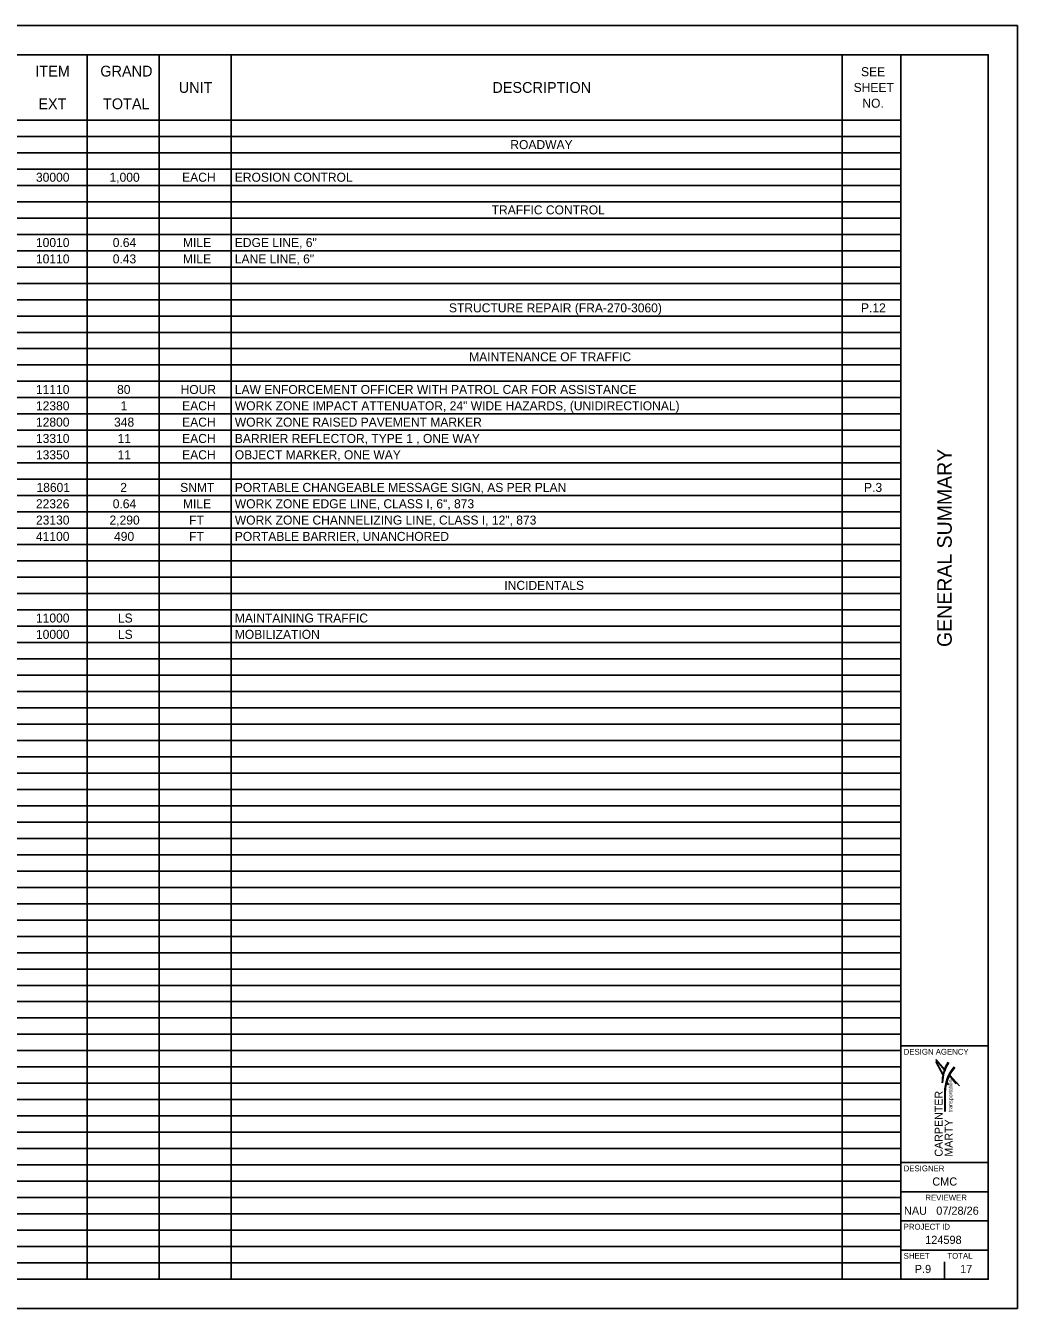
# Model space of a CAD drawing. Extents: x 0 to 34, y 0 to 22.
# Drawn here: x 16.99 to 34, y 0 to 22 of the extents above; entities that cross this region are included whole.
import ezdxf

# ---------------------------------------------------------------- set-up
doc = ezdxf.new("R2010")
doc.units = 0
for name, color, linetype in [('Default', 7, 'Continuous'), ('SH_Border', 7, 'Continuous'), ('SH_Cut_Line', 7, 'Continuous'), ('SH_Data', 7, 'Continuous'), ('SH_Text', 7, 'Continuous')]:
    doc.layers.add(name, color=color, linetype=linetype)

msp = doc.modelspace()

# ---------------------------------------------------------------- linework, layer by layer
at = {"layer": 'Default'}
for p, q in [((1.5, 21.5), (32, 21.5)), ((18.04308, 21.5), (18.04308, 0.5)), ((19.27858, 21.5), (19.27858, 0.5)), ((20.51407, 21.5), (20.51407, 0.5)), ((30.99485, 21.5), (30.99485, 0.5)), ((32, 21.5), (32, 0.5)), ((1.5, 20.38), (32, 20.38)), ((1.5, 20.1), (32, 20.1)), ((1.5, 19.82), (32, 19.82)), ((1.5, 19.54), (32, 19.54)), ((1.5, 19.26), (32, 19.26)), ((1.5, 18.98), (32, 18.98)), ((1.5, 18.7), (32, 18.7)), ((1.5, 18.42), (32, 18.42)), ((1.5, 18.14), (32, 18.14)), ((1.5, 17.86), (32, 17.86)), ((1.5, 17.58), (32, 17.58)), ((1.5, 17.3), (32, 17.3)), ((1.5, 17.02), (32, 17.02)), ((1.5, 16.74), (32, 16.74)), ((1.5, 16.46), (32, 16.46)), ((1.5, 16.18), (32, 16.18)), ((1.5, 15.9), (32, 15.9)), ((1.5, 15.62), (32, 15.62)), ((1.5, 15.34), (32, 15.34)), ((1.5, 15.06), (32, 15.06)), ((1.5, 14.78), (32, 14.78)), ((1.5, 14.5), (32, 14.5)), ((1.5, 14.22), (32, 14.22)), ((1.5, 13.94), (32, 13.94)), ((1.5, 13.66), (32, 13.66)), ((1.5, 13.38), (32, 13.38)), ((1.5, 13.1), (32, 13.1)), ((1.5, 12.82), (32, 12.82)), ((1.5, 12.54), (32, 12.54)), ((1.5, 12.26), (32, 12.26)), ((1.5, 11.98), (32, 11.98)), ((1.5, 11.7), (32, 11.7)), ((1.5, 11.42), (32, 11.42)), ((1.5, 11.14), (32, 11.14)), ((1.5, 10.86), (32, 10.86)), ((1.5, 10.58), (32, 10.58)), ((1.5, 10.3), (32, 10.3)), ((1.5, 10.02), (32, 10.02)), ((1.5, 9.74), (32, 9.74)), ((1.5, 9.46), (32, 9.46)), ((1.5, 9.18), (32, 9.18)), ((1.5, 8.9), (32, 8.9)), ((1.5, 8.62), (32, 8.62)), ((1.5, 8.34), (32, 8.34)), ((1.5, 8.06), (32, 8.06)), ((1.5, 7.78), (32, 7.78)), ((1.5, 7.5), (32, 7.5)), ((1.5, 7.22), (32, 7.22)), ((1.5, 6.94), (32, 6.94)), ((1.5, 6.66), (32, 6.66)), ((1.5, 6.38), (32, 6.38)), ((1.5, 6.1), (32, 6.1)), ((1.5, 5.82), (32, 5.82)), ((1.5, 5.54), (32, 5.54)), ((1.5, 5.26), (32, 5.26)), ((1.5, 4.98), (32, 4.98)), ((1.5, 4.7), (32, 4.7)), ((1.5, 4.42), (32, 4.42)), ((1.5, 4.14), (32, 4.14)), ((1.5, 3.86), (32, 3.86)), ((1.5, 3.58), (32, 3.58)), ((1.5, 3.3), (32, 3.3)), ((1.5, 3.02), (32, 3.02)), ((1.5, 2.74), (32, 2.74)), ((1.5, 2.46), (32, 2.46)), ((1.5, 2.18), (32, 2.18)), ((1.5, 1.9), (32, 1.9)), ((1.5, 1.62), (32, 1.62)), ((1.5, 1.34), (32, 1.34)), ((1.5, 1.06), (32, 1.06)), ((1.5, 0.78), (32, 0.78)), ((1.5, 0.5), (32, 0.5))]:
    msp.add_line(p, q, dxfattribs=at)
at = {"layer": 'SH_Border'}
for p, q in [((32, 0.5), (32, 21.5)), ((32, 4.5), (33.5, 4.5)), ((32, 2.5), (33.5, 2.5)), ((32, 2), (33.5, 2)), ((32, 1.5), (33.5, 1.5)), ((32, 1), (33.5, 1))]:
    msp.add_line(p, q, dxfattribs=at)
msp.add_lwpolyline([(1.5, 21.5), (33.5, 21.5), (33.5, 0.5), (1.5, 0.5)], close=True, dxfattribs=at)
at = {"layer": 'SH_Cut_Line'}
msp.add_lwpolyline([(0, 0), (34, 0), (34, 22), (0, 22)], close=True, dxfattribs=at)
at = {"layer": 'SH_Data'}
for p, q in [((32.75, 3.5), (32.75, 3.5)), ((32.375, 0.675), (32.375, 0.675)), ((32.75, 0.5), (32.75, 0.8))]:
    msp.add_line(p, q, dxfattribs=at)
at = {"layer": 'SH_Text'}
for p, q in [((32.72069, 4.01649), (32.60162, 4.23177)), ((32.95166, 3.8527), (32.83407, 3.99137)), ((32.83913, 4.00169), (33.00597, 3.81618)), ((32.8109, 3.84047), (32.78964, 3.88)), ((32.82016, 3.83352), (32.79149, 3.88608)), ((32.755, 3.3776), (32.755, 3.70391)), ((32.76174, 3.3776), (32.76174, 3.70408))]:
    msp.add_line(p, q, dxfattribs=at)
for points in [[(32.74615, 4.10431), (32.60113, 4.26615)], [(32.60113, 4.26605), (32.74381, 4.0978)], [(32.72069, 4.01649), (32.60162, 4.23177)], [(32.60162, 4.23173), (32.71946, 4.01079)]]:
    msp.add_lwpolyline(points, dxfattribs=at)
for centre, radius, start, end in [((33.4324, 3.85993), 0.72071, 149.570417, 179.552883), ((33.37304, 3.86159), 0.65428, 147.142265, 179.652527), ((33.42552, 3.70404), 0.67052, 139.289845, 180.01062), ((33.43327, 3.68775), 0.67173, 138.512563, 178.6075)]:
    msp.add_arc(centre, radius, start, end, dxfattribs=at)

# ---------------------------------------------------------------- texts
at = {"layer": 'Default'}
for s, height, p in [('ITEM', 0.185472, (17.15496, 21.12726)), ('GRAND', 0.185472, (18.26982, 21.12726)), ('SEE ', 0.15456, (31.31887, 21.1332)), ('UNIT', 0.185472, (19.61506, 20.84726)), ('DESCRIPTION', 0.185472, (24.9946, 20.84726)), ('SHEET ', 0.15456, (31.19159, 20.86272)), ('EXT', 0.185472, (17.20667, 20.56726)), ('TOTAL', 0.185472, (18.31574, 20.56726)), ('NO.', 0.15456, (31.34138, 20.59224)), ('ROADWAY', 0.15456, (25.30316, 19.88272)), ('30000', 0.15456, (17.16611, 19.32272)), ('1,000', 0.15456, (18.42792, 19.32272)), ('EACH', 0.15456, (19.67367, 19.32272)), ('EROSION CONTROL', 0.15456, (20.5769, 19.32272)), ('TRAFFIC CONTROL', 0.15456, (24.98295, 18.76272)), ('10010', 0.15456, (17.16611, 18.20272)), ('0.64', 0.15456, (18.48299, 18.20272)), ('MILE', 0.15456, (19.68796, 18.20272)), ('EDGE LINE, 6"', 0.15456, (20.5769, 18.20272)), ('10110', 0.15456, (17.16611, 17.92272)), ('0.43', 0.15456, (18.48299, 17.92272)), ('MILE', 0.15456, (19.68796, 17.92272)), ('LANE LINE, 6"', 0.15456, (20.5769, 17.92272)), ('STRUCTURE REPAIR (FRA-270-3060)', 0.15456, (24.25026, 17.08272)), ('P.12', 0.15456, (31.31818, 17.08272)), ('MAINTENANCE OF TRAFFIC', 0.15456, (24.59704, 16.24272)), ('11110', 0.15456, (17.16611, 15.68272)), ('80', 0.15456, (18.55729, 15.68272)), ('HOUR', 0.15456, (19.64662, 15.68272)), ('LAW ENFORCEMENT OFFICER WITH PATROL CAR FOR ASSISTANCE', 0.15456, (20.5769, 15.68272)), ('12380', 0.15456, (17.16611, 15.40272)), ('1', 0.15456, (18.61828, 15.40272)), ('EACH', 0.15456, (19.67367, 15.40272)), ('WORK ZONE IMPACT ATTENUATOR, 24" WIDE HAZARDS, (UNIDIRECTIONAL)', 0.15456, (20.5769, 15.40272)), ('12800', 0.15456, (17.16611, 15.12272)), ('348', 0.15456, (18.50594, 15.12272)), ('EACH', 0.15456, (19.67367, 15.12272)), ('WORK ZONE RAISED PAVEMENT MARKER', 0.15456, (20.5769, 15.12272)), ('13310', 0.15456, (17.16611, 14.84272)), ('11', 0.15456, (18.56638, 14.84272)), ('EACH', 0.15456, (19.67367, 14.84272)), ('BARRIER REFLECTOR, TYPE 1 , ONE WAY', 0.15456, (20.5769, 14.84272)), ('13350', 0.15456, (17.16611, 14.56272)), ('11', 0.15456, (18.56638, 14.56272)), ('EACH', 0.15456, (19.67367, 14.56272)), ('OBJECT MARKER, ONE WAY', 0.15456, (20.5769, 14.56272)), ('18601', 0.15456, (17.1752, 14.00272)), ('2', 0.15456, (18.61229, 14.00272)), ('SNMT', 0.15456, (19.6393, 14.00272)), ('PORTABLE CHANGEABLE MESSAGE SIGN, AS PER PLAN', 0.15456, (20.5769, 14.00272)), ('P.3', 0.15456, (31.37044, 14.00272)), ('22326', 0.15456, (17.16556, 13.72272)), ('0.64', 0.15456, (18.48299, 13.72272)), ('MILE', 0.15456, (19.68796, 13.72272)), ('WORK ZONE EDGE LINE, CLASS I, 6", 873', 0.15456, (20.5769, 13.72272)), ('23130', 0.15456, (17.16611, 13.44272)), ('2,290', 0.15456, (18.42792, 13.44272)), ('FT', 0.15456, (19.79223, 13.44272)), ('WORK ZONE CHANNELIZING LINE, CLASS I, 12", 873', 0.15456, (20.5769, 13.44272)), ('41100', 0.15456, (17.16611, 13.16272)), ('490', 0.15456, (18.50539, 13.16272)), ('FT', 0.15456, (19.79223, 13.16272)), ('PORTABLE BARRIER, UNANCHORED', 0.15456, (20.5769, 13.16272)), ('INCIDENTALS', 0.15456, (25.20072, 12.32272)), ('11000', 0.15456, (17.16611, 11.76272)), ('LS', 0.15456, (18.57176, 11.76272)), ('MAINTAINING TRAFFIC', 0.15456, (20.5769, 11.76272)), ('10000', 0.15456, (17.16611, 11.48272)), ('LS', 0.15456, (18.57176, 11.48272)), ('MOBILIZATION', 0.15456, (20.5769, 11.48272))]:
    msp.add_text(s, height=height, dxfattribs=at).set_placement(p)
at = {"layer": 'SH_Data'}
msp.add_text('GENERAL SUMMARY', height=0.25, rotation=90, dxfattribs=at).set_placement((32.875, 11.34354))
for s, height, p in [('DESIGN AGENCY', 0.1, (32.05, 4.35)), ('DESIGNER', 0.1, (32.05, 2.35)), ('CMC', 0.14, (32.54105, 2.105)), ('REVIEWER', 0.1, (32.42183, 1.85)), ('NAU', 0.14, (32.05505, 1.605)), ('07/28/26', 0.14, (32.60894, 1.605)), ('PROJECT ID', 0.1, (32.05, 1.35)), ('124598', 0.14, (32.41932, 1.105)), ('SHEET', 0.1, (32.05, 0.85)), ('TOTAL', 0.1, (32.8, 0.85)), ('P.9', 0.14, (32.23986, 0.605)), ('17', 0.14, (33.01832, 0.605))]:
    msp.add_text(s, height=height, dxfattribs=at).set_placement(p)
at = {"layer": 'SH_Text'}
for s, height, p in [('transportation', 0.0664908, (32.88493, 3.36395)), ('CARPENTER ', 0.13675, (32.71908, 2.60179)), ('MARTY', 0.13675, (32.89062, 2.60179))]:
    msp.add_text(s, height=height, rotation=90, dxfattribs=at).set_placement(p)

doc.saveas('drawing.dxf')
